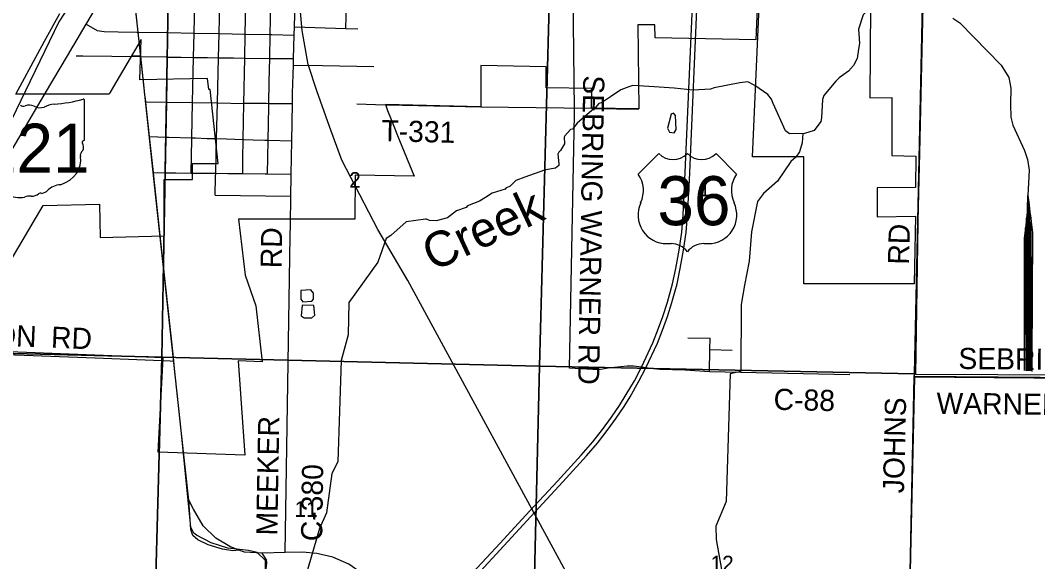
# Model space of a CAD drawing. Extents: x 0 to 68.9, y -26.1 to 22.
# Drawn here: x 4.831 to 7.562, y 15.348 to 16.802 of the extents above; entities that cross this region are included whole.
import ezdxf

# ---------------------------------------------------------------- set-up
doc = ezdxf.new("R2010")
doc.units = 0
for name, color, linetype in [('GM_X_City_Street', 7, 'Continuous'), ('GM_X_Corporation', 7, 'Continuous'), ('GM_X_County_Road', 7, 'Continuous'), ('GM_X_County_Road_Text', 7, 'Continuous'), ('GM_X_Minor_Lake', 7, 'Continuous'), ('GM_X_Minor_River', 7, 'Continuous'), ('GM_X_Minor_River_Text', 7, 'Continuous'), ('GM_X_Rail_Line', 7, 'Continuous'), ('GM_X_Section_Text', 7, 'Continuous'), ('GM_X_State_Location', 7, 'Continuous'), ('GM_X_State_Route', 7, 'Continuous'), ('GM_X_State_Shield', 7, 'Continuous'), ('GM_X_Township_Road', 7, 'Continuous'), ('GM_X_Township_Road_Text', 7, 'Continuous'), ('GM_X_US_Location', 7, 'Continuous'), ('GM_X_US_Route', 7, 'Continuous'), ('GM_X_US_Shield', 7, 'Continuous')]:
    doc.layers.add(name, color=color, linetype=linetype)

msp = doc.modelspace()

# ---------------------------------------------------------------- linework, layer by layer
at = {"layer": 'GM_X_City_Street'}
for q in [(5.355, 16.3818), (5.557, 16.3301)]:
    msp.add_line((5.3538, 16.3326), q, dxfattribs=at)
for points in [[(5.2204, 16.3928), (5.2221, 16.4886), (5.2237, 16.5823), (5.2258, 16.7038), (5.2269, 16.7693), (5.229, 16.8943), (5.2297, 16.9315), (5.2306, 16.9886), (5.2318, 17.055), (5.2325, 17.1002), (5.2349, 17.1158), (5.2369, 17.1288), (5.238, 17.1362), (5.2384, 17.1685), (5.2385, 17.1735), (5.2391, 17.2232), (5.2396, 17.2617), (5.2399, 17.2783), (5.2411, 17.3708)], [(5.355, 16.3818), (5.3552, 16.3914), (5.3574, 16.4845), (5.3597, 16.5803), (5.3627, 16.702), (5.3642, 16.7667), (5.3672, 16.8917), (5.3696, 16.9888), (5.3724, 17.1068), (5.3734, 17.1485), (5.3752, 17.2213), (5.3765, 17.2757), (5.3778, 17.3317), (5.3791, 17.3851)], [(5.2891, 16.3921), (5.2911, 16.4829), (5.2912, 16.4865), (5.2932, 16.5813), (5.2959, 16.7029), (5.2973, 16.768), (5.3, 16.893), (5.3021, 16.9887), (5.3049, 17.1178), (5.3053, 17.1385)], [(5.4974, 16.5698), (5.4976, 16.5784), (5.4988, 16.6382), (5.5, 16.7002), (5.5013, 16.764), (5.5039, 16.8889), (5.5059, 16.9879), (5.5078, 17.0849)], [(5.7047, 16.7803), (5.7067, 16.8783), (5.7068, 16.8842), (5.7086, 16.9764), (5.7086, 16.9774)], [(5.5609, 16.5776), (5.5617, 16.6069), (5.5637, 16.6823), (5.5641, 16.6994), (5.5658, 16.7628), (5.5664, 16.7848), (5.5691, 16.8874)], [(5.0073, 16.7919), (5.0368, 16.7754), (5.0557, 16.7726), (5.0929, 16.7719)], [(5.0929, 16.7719), (5.1432, 16.7709), (5.147, 16.7709), (5.2237, 16.7694)], [(5.2237, 16.7694), (5.2269, 16.7693), (5.2973, 16.768), (5.3642, 16.7667), (5.4345, 16.7653), (5.5013, 16.764), (5.5054, 16.764), (5.5658, 16.7628)], [(5.5664, 16.7848), (5.7047, 16.7803), (5.7362, 16.7793)], [(4.9809, 16.7068), (4.998, 16.7068), (5.1541, 16.7048), (5.2222, 16.7039), (5.2258, 16.7038), (5.2625, 16.7034), (5.2959, 16.7029), (5.3328, 16.7024), (5.3627, 16.702), (5.4032, 16.7015), (5.433, 16.7011), (5.5, 16.7002), (5.5641, 16.6994)], [(5.5637, 16.6823), (5.6422, 16.6808), (5.7798, 16.6783)], [(5.1673, 16.5832), (5.2237, 16.5823), (5.2932, 16.5813), (5.3597, 16.5803), (5.4303, 16.5792)], [(5.4277, 16.3907), (5.4282, 16.4306), (5.4289, 16.4823), (5.4303, 16.5792)], [(5.4956, 16.4802), (5.4974, 16.5687), (5.4974, 16.5698)], [(5.1774, 16.49), (5.2221, 16.4886), (5.229, 16.4884), (5.2912, 16.4865), (5.3013, 16.4862), (5.3322, 16.4852), (5.3574, 16.4845), (5.3838, 16.4837), (5.4289, 16.4823), (5.4561, 16.4814), (5.4871, 16.4805), (5.4956, 16.4802), (5.5593, 16.4783)], [(5.4938, 16.39), (5.4956, 16.4794), (5.4956, 16.4802)], [(5.1879, 16.3931), (5.2204, 16.3928), (5.2479, 16.3925), (5.2891, 16.3921), (5.3179, 16.3918), (5.3552, 16.3914), (5.3879, 16.3911), (5.4277, 16.3907), (5.4879, 16.3901), (5.4938, 16.39), (5.5579, 16.3894)]]:
    msp.add_lwpolyline(points, dxfattribs=at)
at = {"layer": 'GM_X_Corporation'}
for points in [[(4.2396, 16.9168), (5.2285, 16.9015), (5.2101, 15.8972), (4.1977, 15.9225), (4.218, 16.9165)], [(5.2394, 16.9012), (6.2515, 16.877), (6.224, 15.8733), (5.2101, 15.8972), (5.2285, 16.9015)], [(6.2515, 16.877), (7.2528, 16.8431), (7.2305, 15.8522), (6.224, 15.8733)], [(7.2528, 16.8431), (8.024, 16.8186), (8.019, 15.8387), (7.2304, 15.8453), (7.2305, 15.8522)], [(4.1977, 15.9225), (5.2101, 15.8972), (5.1829, 14.8851), (4.1789, 14.914)], [(5.2101, 15.8972), (6.224, 15.8733), (6.2001, 14.86), (5.1829, 14.8851)], [(6.224, 15.8733), (7.2305, 15.8522), (7.2304, 15.8453), (7.2092, 14.8389), (6.2001, 14.86)], [(8.019, 15.8387), (8.0065, 14.829), (7.2092, 14.8389), (7.2304, 15.8453)]]:
    msp.add_lwpolyline(points, close=True, dxfattribs=at)
for points in [[(6.8124, 16.9207), (6.8047, 16.7504), (6.5345, 16.7554), (6.5343, 16.7902), (6.4882, 16.7903), (6.4908, 16.5644), (6.3641, 16.5666), (6.3652, 16.6188), (6.2425, 16.6209), (6.2425, 16.6777), (6.0664, 16.6807), (6.0664, 16.5702), (5.8105, 16.5763), (5.816, 16.5599), (5.8257, 16.5362), (5.8484, 16.4796), (5.8876, 16.384), (5.7299, 16.3863), (5.7288, 16.2682), (5.4159, 16.2681), (5.4343, 16.1179), (5.4627, 16.0356), (5.4797, 15.8849), (5.4154, 15.8874), (5.4331, 15.6338), (5.2007, 15.6419), (5.214, 15.8952), (4.6626, 15.9168), (4.8916, 16.3044), (5.0431, 16.3084), (5.0447, 16.2184), (5.217, 16.223), (5.2169, 16.3745), (5.2927, 16.3746), (5.2927, 16.4181), (5.3618, 16.4181), (5.3402, 16.6169), (5.3365, 16.6166), (5.3333, 16.6464), (5.1514, 16.6427), (5.1552, 16.7505), (5.0872, 16.6354), (5.071, 16.608), (5.0687, 16.6041), (4.8187, 16.604), (4.8955, 16.7462), (4.9363, 16.8211)], [(7.1128, 16.8426), (7.1107, 16.5937), (7.1704, 16.5947), (7.1704, 16.4393), (7.2348, 16.4373), (7.234, 16.3531), (7.1304, 16.3524), (7.1304, 16.2744), (7.2332, 16.2761), (7.2303, 16.0947), (6.934, 16.0947), (6.934, 16.4357), (6.796, 16.4357), (6.8179, 16.9198)], [(7.675, 15.8489), (7.2349, 15.8509), (7.243, 16.3744), (7.2446, 16.4546), (7.2541, 16.8466)]]:
    msp.add_lwpolyline(points, dxfattribs=at)
at = {"layer": 'GM_X_County_Road'}
for p, q in [((6.318, 16.5639), (6.3155, 16.7937)), ((5.4905, 16.5785), (5.4303, 16.5792)), ((6.3179, 16.5535), (6.318, 16.5639)), ((6.6224, 15.9494), (6.6824, 15.9481)), ((6.6817, 15.9176), (6.6824, 15.9481)), ((4.4899, 15.9162), (5.0318, 15.8951)), ((5.0318, 15.8951), (5.2326, 15.8872)), ((6.6803, 15.8582), (6.6817, 15.9176)), ((6.6817, 15.9176), (6.7417, 15.9163)), ((5.2326, 15.8872), (5.2426, 15.8868))]:
    msp.add_line(p, q, dxfattribs=at)
for points in [[(5.4303, 16.5792), (5.433, 16.7011), (5.4345, 16.7653), (5.4373, 16.8904), (5.4395, 16.9889)], [(6.3155, 16.7937), (6.3147, 16.8667), (6.3114, 16.8714), (6.3014, 16.8716), (6.2993, 16.8716)], [(5.5609, 16.5776), (5.4976, 16.5784), (5.4905, 16.5785)], [(5.5579, 16.3847), (5.5579, 16.3894), (5.5593, 16.4783), (5.5609, 16.5776)], [(7.0577, 15.8496), (6.6803, 15.8582), (6.6155, 15.8626), (6.5471, 15.8644), (6.5224, 15.8672), (6.5094, 15.8686), (6.4979, 15.8701), (6.4766, 15.8728), (6.4598, 15.8729), (6.4089, 15.8678), (6.3829, 15.8628), (6.3052, 15.868), (6.3179, 16.5493), (6.3179, 16.5535)], [(5.5553, 16.2232), (5.5558, 16.2527), (5.557, 16.3301), (5.5579, 16.3847)], [(5.5417, 15.3723), (5.5553, 16.2222), (5.5553, 16.2232)], [(5.4168, 15.3788), (5.401, 15.3765), (5.3734, 15.3808), (5.335, 15.3933), (5.3074, 15.4067), (5.2936, 15.4178), (5.288, 15.434), (5.2829, 15.5132)], [(5.4413, 14.8553), (5.4423, 14.865), (5.4435, 14.877), (5.4484, 14.9277), (5.4712, 15.1394), (5.4871, 15.297), (5.4923, 15.3449), (5.4911, 15.3529), (5.4798, 15.3701)]]:
    msp.add_lwpolyline(points, dxfattribs=at)
at = {"layer": 'GM_X_Minor_Lake'}
for points in [[(6.5844, 16.553), (6.5775, 16.5505), (6.5677, 16.5127), (6.5735, 16.5019)], [(6.5735, 16.5019), (6.5857, 16.5002), (6.5916, 16.5092), (6.5896, 16.5468), (6.5844, 16.553)], [(5.6129, 16.0476), (5.6172, 16.0532), (5.6178, 16.0696), (5.6107, 16.0784), (5.5833, 16.0765)], [(5.5833, 16.0765), (5.5838, 16.0532), (5.589, 16.0463), (5.6129, 16.0476)], [(5.587, 16.0372), (5.5844, 16.0084), (5.5926, 16.0026), (5.6132, 16.0031)], [(5.6132, 16.0031), (5.6216, 16.0102), (5.6185, 16.0361), (5.587, 16.0372)]]:
    msp.add_lwpolyline(points, dxfattribs=at)
at = {"layer": 'GM_X_Minor_River'}
for points in [[(5.0237, 17.3401), (4.9995, 17.1995), (5.0331, 17.124), (5.0533, 17.1017), (5.0403, 17.0779), (5.0084, 17.0328), (5.0023, 16.9428), (5.0093, 16.9294), (5.0102, 16.9161), (4.9337, 16.7983), (4.5504, 16.0051), (4.5433, 15.9938)], [(7.2417, 17.1124), (7.2285, 17.0777), (7.215, 17.0291), (7.2105, 16.9836), (7.2049, 16.96), (7.2064, 16.9536), (7.2042, 16.9482), (7.2011, 16.9479), (7.1588, 16.9182), (7.138, 16.9003), (7.1255, 16.8798), (7.1251, 16.8771), (7.1233, 16.8471), (7.1074, 16.8308), (7.0934, 16.8171), (7.081, 16.7791), (7.0834, 16.7404), (7.0804, 16.7252), (7.077, 16.6994), (7.0668, 16.6808), (7.054, 16.666), (7.0283, 16.6477), (7.0197, 16.6386)], [(6.802, 16.6276), (6.7838, 16.6374), (6.7618, 16.6343), (6.6932, 16.6209), (6.683, 16.6178), (6.6371, 16.6147), (6.5855, 16.6199), (6.5324, 16.624), (6.4752, 16.6273), (6.4642, 16.6235), (6.4422, 16.6155), (6.415, 16.5969), (6.3908, 16.5805), (6.3836, 16.579), (6.3737, 16.5675), (6.3707, 16.5683), (6.3707, 16.5656), (6.3257, 16.5261), (6.3128, 16.5101), (6.3075, 16.5086), (6.2924, 16.4918), (6.2901, 16.4884), (6.2913, 16.4702), (6.2804, 16.4527), (6.2758, 16.4478), (6.2739, 16.4428), (6.2763, 16.417), (6.2759, 16.4125), (6.2672, 16.4049), (6.2411, 16.4007), (6.2373, 16.3999), (6.185, 16.3812), (6.1612, 16.372), (6.1456, 16.3564), (6.1339, 16.3518), (6.132, 16.3484), (6.0972, 16.3377), (6.079, 16.3263), (6.0631, 16.316), (6.0313, 16.3042), (6.0275, 16.2996)], [(7.0197, 16.6386), (6.9873, 16.6007), (6.9837, 16.5893), (6.9816, 16.54), (6.9795, 16.5301), (6.9612, 16.5065), (6.9359, 16.4986), (6.8955, 16.4971), (6.885, 16.5057), (6.8517, 16.5785), (6.847, 16.5903), (6.837, 16.6031), (6.802, 16.6276)], [(6.931, 16.4985), (6.9294, 16.4734), (6.9221, 16.4489), (6.9124, 16.4344), (6.8991, 16.4227), (6.8633, 16.3706), (6.8256, 16.3373), (6.8092, 16.3158), (6.7934, 16.2341), (6.7868, 16.1554), (6.7743, 16.0911), (6.7654, 16.0389)], [(6.0275, 16.2996), (6.0014, 16.2905), (5.9775, 16.2714), (5.9472, 16.2638), (5.9294, 16.2649), (5.9214, 16.2683), (5.918, 16.2683), (5.866, 16.2613)], [(5.866, 16.2613), (5.8254, 16.2239), (5.8128, 16.2158), (5.7904, 16.1522), (5.7129, 16.044), (5.7106, 15.9576), (5.6916, 15.8883), (5.6827, 15.6158), (5.6669, 15.5849), (5.6521, 15.4785), (5.6339, 15.4372), (5.5869, 15.2768), (5.5975, 15.1844), (5.5966, 15.1566), (5.379, 14.6444), (5.3722, 14.6003), (5.2503, 14.1)], [(6.7654, 16.0389), (6.7643, 15.8587), (6.736, 15.8528), (6.7256, 15.5095)], [(6.7256, 15.5095), (6.698, 15.4431), (6.6982, 15.4069), (6.7125, 15.327), (6.7031, 15.2797), (6.7015, 15.2335), (6.7019, 15.2236), (6.7086, 15.1238), (6.7064, 15.0838), (6.6965, 15.0437), (6.6971, 15.0055), (6.7303, 14.9142), (6.7398, 14.8585), (6.7315, 14.8191), (6.7371, 14.7949), (6.7925, 14.6739), (6.794, 14.6513), (6.7756, 14.6077), (6.7386, 14.501), (6.7034, 14.4213)]]:
    msp.add_lwpolyline(points, dxfattribs=at)
at = {"layer": 'GM_X_Rail_Line'}
for p, q in [((7.5375, 16.314), (7.5408, 16.2876)), ((7.5345, 16.2955), (7.5316, 16.2706)), ((7.537, 15.8607), (7.5345, 16.2955)), ((7.5432, 15.8607), (7.5408, 16.2876)), ((7.5339, 15.8607), (7.5316, 16.2706)), ((7.5462, 15.8876), (7.5441, 16.2613)), ((7.5308, 15.8606), (7.5286, 16.2447)), ((7.5462, 15.8876), (7.5461, 15.859))]:
    msp.add_line(p, q, dxfattribs=at)
for points in [[(5.3603, 14.1), (5.4108, 14.554), (5.4493, 14.931), (5.4886, 15.3274), (5.4889, 15.3505), (5.4662, 15.3724), (5.4429, 15.3781), (5.388, 15.3842), (5.3426, 15.3979), (5.3038, 15.4193), (5.2961, 15.4246), (5.2885, 15.4402), (5.2608, 15.718), (5.1953, 16.319), (5.1234, 16.9884), (5.1371, 16.996), (5.443, 16.9855), (5.445, 17.1132)], [(6.9557, 14.1), (6.658, 14.6501), (6.2728, 15.3624), (5.8705, 16.1031), (5.7903, 16.2402), (5.6933, 16.4263), (5.661, 16.5169), (5.6263, 16.6127), (5.6035, 16.684), (5.587, 16.7753), (5.5776, 16.8861), (5.579, 16.9902), (5.581, 17.0911)], [(7.334, 16.8085), (7.3529, 16.7961), (7.4639, 16.6819), (7.4844, 16.649), (7.4893, 16.6202), (7.4885, 16.5758), (7.4893, 16.5421), (7.4951, 16.5208), (7.5263, 16.4525), (7.5345, 16.4287), (7.5387, 16.3999), (7.5354, 16.3317)], [(7.5345, 16.2955), (7.5354, 16.3317), (7.5375, 16.314)], [(7.5401, 15.8607), (7.5377, 16.2955), (7.5375, 16.314)], [(7.5408, 16.2876), (7.5428, 16.2717), (7.5441, 16.2613)], [(7.5316, 16.2706), (7.5304, 16.261), (7.5286, 16.2447)], [(7.5441, 16.2613), (7.5477, 16.2322), (7.5462, 15.8876)], [(7.5286, 16.2447), (7.5255, 16.2166), (7.5255, 15.8615)]]:
    msp.add_lwpolyline(points, dxfattribs=at)
at = {"layer": 'GM_X_State_Route'}
for p, q in [((5.0089, 16.7946), (5.0297, 16.8299)), ((5.2627, 15.7), (5.2447, 15.8672))]:
    msp.add_line(p, q, dxfattribs=at)
for points in [[(5.1653, 16.6014), (5.1632, 16.6213), (5.1541, 16.7048), (5.147, 16.7709), (5.1294, 16.9329), (5.1234, 16.9884)], [(4.9727, 16.7333), (4.9742, 16.736), (5.0073, 16.7919), (5.0089, 16.7946)], [(4.8865, 16.5875), (4.8885, 16.5909), (4.8983, 16.6074), (4.9569, 16.7066), (4.9727, 16.7333)], [(4.6958, 16.2647), (4.6968, 16.2664), (4.8865, 16.5875)], [(5.1675, 16.5812), (5.1673, 16.5832), (5.1664, 16.5915), (5.1653, 16.6014)], [(5.1852, 16.4178), (5.1774, 16.49), (5.1675, 16.5812)], [(5.1889, 16.3832), (5.1879, 16.3931), (5.1852, 16.4178)], [(5.2426, 15.8868), (5.2415, 15.8968), (5.2061, 16.2244), (5.1889, 16.3832)], [(5.2447, 15.8672), (5.2437, 15.877), (5.2426, 15.8868)], [(5.4798, 15.3701), (5.432, 15.3732), (5.4168, 15.3788), (5.3932, 15.3882), (5.3551, 15.4112), (5.3213, 15.4441), (5.2951, 15.4885), (5.2829, 15.5132), (5.2627, 15.7)], [(5.7659, 15.302), (5.7456, 15.3179), (5.7127, 15.3407), (5.6697, 15.3595), (5.6267, 15.3696), (5.5885, 15.3736), (5.5417, 15.3723), (5.4798, 15.3701)]]:
    msp.add_lwpolyline(points, dxfattribs=at)
at = {"layer": 'GM_X_State_Shield'}
for p, q in [((5.0033, 16.4825), (5.0033, 16.5872)), ((5.0032, 16.4825), (5.0033, 16.4825))]:
    msp.add_line(p, q, dxfattribs=at)
for centre, major_axis, start_param, end_param in [((4.9305, 16.5211), (0.0703, 0), 1.699011, 2.107814), ((4.8859, 16.8551), (0.3495, 0), 4.814394, 5.042369), ((4.9996, 16.5876), (0.00367, 0), 6.141152, 7.989035), ((4.8389, 16.5802), (0.0107, 0), 3.836095, 5.185415), ((4.8546, 16.5571), (0.0222, 0), 0.950623, 2.079405), ((4.8833, 16.5888), (0.0267, 0), 4.081561, 5.145723), ((5.0024, 16.4748), (0.00568, 0), 1.883978, 3.671073), ((4.9663, 16.4616), (0.0341, 0), 5.934695, 6.695948), ((4.9994, 16.4821), (0.00393, 0), 5.05454, 6.418171), ((5.0164, 16.4387), (0.0248, 0), 2.387724, 3.262537), ((4.9055, 16.4254), (0.0874, 0), 5.101752, 6.440018), ((4.9423, 16.3225), (0.0479, 0), 1.647645, 2.488434), ((4.8281, 16.3661), (0.0501, 0), 4.026481, 4.996735), ((4.8607, 16.3511), (0.0267, 0), 4.691044, 5.507374), ((4.8849, 16.3317), (0.00752, 0), 1.147584, 2.315152), ((4.8817, 16.3593), (0.0282, 0), 4.937069, 5.64225), ((4.857, 16.2969), (0.0412, 0), 1.495662, 1.94098)]:
    msp.add_ellipse(centre, major_axis=major_axis, ratio=0.8, start_param=start_param, end_param=end_param, dxfattribs=at)
at = {"layer": 'GM_X_Township_Road'}
for p, q in [((5.1298, 16.7066), (5.1539, 16.7068)), ((5.7339, 16.5776), (5.7843, 16.5764)), ((5.7843, 16.5764), (5.8146, 16.5757)), ((5.8146, 16.5757), (6.067, 16.5696)), ((6.3703, 16.5659), (6.491, 16.5639)), ((7.2432, 16.3749), (7.2449, 16.4456)), ((7.2307, 15.8496), (7.2432, 16.3749)), ((7.209, 14.835), (7.232, 15.8435))]:
    msp.add_line(p, q, dxfattribs=at)
for points in [[(7.2449, 16.4456), (7.2449, 16.4466), (7.2542, 16.84)], [(6.067, 16.5696), (6.3643, 16.566), (6.3703, 16.5659)], [(7.232, 15.8435), (7.2313, 15.8451), (7.2307, 15.8496)], [(8.2654, 15.8336), (7.764, 15.8393), (7.232, 15.8435)]]:
    msp.add_lwpolyline(points, dxfattribs=at)
at = {"layer": 'GM_X_US_Route'}
for points in [[(6.0454, 15.3181), (6.1185, 15.3975), (6.1867, 15.4716), (6.2727, 15.5637), (6.3365, 15.6339), (6.3676, 15.6697), (6.3935, 15.7024), (6.4176, 15.7359), (6.4391, 15.7671), (6.4571, 15.7969), (6.479, 15.8334), (6.4979, 15.8701), (6.5284, 15.9355), (6.5437, 15.9752), (6.5557, 16.0069), (6.5675, 16.0447), (6.5815, 16.0947), (6.5901, 16.1356), (6.5989, 16.185), (6.606, 16.2327), (6.6098, 16.2795), (6.6145, 16.3735), (6.6376, 16.9027)], [(6.5094, 15.8686), (6.5411, 15.9345), (6.5549, 15.9701), (6.5677, 16.0065), (6.5796, 16.0442), (6.5936, 16.0943), (6.6021, 16.1351), (6.6109, 16.1845), (6.618, 16.2322), (6.6218, 16.279), (6.6266, 16.373), (6.6493, 16.8953)], [(6.0556, 15.3101), (6.1394, 15.4015), (6.2009, 15.4689), (6.2873, 15.562), (6.3509, 15.6318), (6.3799, 15.666), (6.4089, 15.7035), (6.4302, 15.7332), (6.4519, 15.7645), (6.4678, 15.7909), (6.491, 15.8329), (6.5094, 15.8686)]]:
    msp.add_lwpolyline(points, dxfattribs=at)
at = {"layer": 'GM_X_US_Shield'}
for p, q in [((6.5444, 16.4441), (6.4894, 16.3891)), ((6.7531, 16.3891), (6.6982, 16.4441)), ((6.5663, 16.2024), (6.5773, 16.2024)), ((6.6652, 16.2024), (6.6762, 16.2024))]:
    msp.add_line(p, q, dxfattribs=at)
for centre, radius, start, end in [((6.5828, 16.4833), 0.0549, 225.573, 314.427), ((6.6597, 16.4833), 0.0549, 225.573, 314.427), ((6.4264, 16.345), 0.0769, 334.5471, 35.0009), ((6.8161, 16.345), 0.0769, 144.9991, 205.4529), ((6.5655, 16.2793), 0.0769, 154.8319, 270.6383), ((6.677, 16.2793), 0.0769, 269.3617, 25.1681), ((6.5773, 16.1474), 0.0549, 36.8699, 90), ((6.6652, 16.1474), 0.0549, 90, 143.1301)]:
    msp.add_arc(centre, radius, start, end, dxfattribs=at)

# ---------------------------------------------------------------- texts
at = {"layer": 'GM_X_County_Road_Text'}
for s, height, rotation, p in [('SEBRING WARNER RD', 0.056818, 269.0179, (6.3419, 16.6551)), ('RD', 0.05682, 89.0123, (5.5321, 16.1359)), ('EIDSON', 0.05682, 357.5672, (4.5822, 15.9362)), ('RD', 0.05682, 357.5313, (4.9122, 15.9228)), ('C-88', 0.05682, 358.6274, (6.8522, 15.756)), ('MEEKER', 0.05682, 88.9979, (5.5205, 15.4176)), ('C-380', 0.05682, 89.1739, (5.6408, 15.4024))]:
    msp.add_text(s, height=height, rotation=rotation, dxfattribs=at).set_placement(p)
at = {"layer": 'GM_X_Minor_River_Text'}
msp.add_text('Creek', height=0.0947, rotation=25.0144, dxfattribs=at).set_placement((5.9383, 16.1264))
at = {"layer": 'GM_X_Section_Text'}
for s, height, p in [('2', 0.0419, (5.7134, 16.3526)), ('1', 0.0419, (6.6526, 16.3297)), ('11', 0.04186, (5.5667, 15.4681)), ('12', 0.04186, (6.6834, 15.3217))]:
    msp.add_text(s, height=height, rotation=0, dxfattribs=at).set_placement(p)
at = {"layer": 'GM_X_State_Location'}
for s in ['s', 'r']:
    msp.add_text(s, height=0.000189, dxfattribs=at).set_placement((4.8348, 16.4654))
at = {"layer": 'GM_X_State_Shield'}
msp.add_text('121', height=0.13184, dxfattribs=at).set_placement((4.7223, 16.3928))
at = {"layer": 'GM_X_Township_Road_Text'}
for s, rotation, p in [('T-331', 358.5957, (5.7993, 16.4778)), ('RD', 88.5189, (7.2161, 16.1453)), ('SEBRING', 359.5188, (7.3486, 15.8654)), ('JOHNS', 88.6728, (7.2027, 15.531)), ('WARNER RD', 359.425, (7.2898, 15.7451))]:
    msp.add_text(s, height=0.05682, rotation=rotation, dxfattribs=at).set_placement(p)
at = {"layer": 'GM_X_US_Location'}
for s in ['0', '/']:
    msp.add_text(s, height=0.000189, dxfattribs=at).set_placement((6.6212, 16.3167))
msp.add_text('36', height=0.000189, rotation=0, dxfattribs=at).set_placement((6.5821, 16.2775))
at = {"layer": 'GM_X_US_Shield'}
msp.add_text('36', height=0.13184, dxfattribs=at).set_placement((6.5408, 16.2518))

doc.saveas('drawing.dxf')
